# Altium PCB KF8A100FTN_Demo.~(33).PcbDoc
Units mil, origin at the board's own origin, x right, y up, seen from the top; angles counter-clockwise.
Board outline 6000 x 4000 mil, 2 copper layers (Top Layer, Bottom Layer); 25 components, 35 nets, 113 pads, 0 vias.
Unrouted connection lines stored in the file: 7.
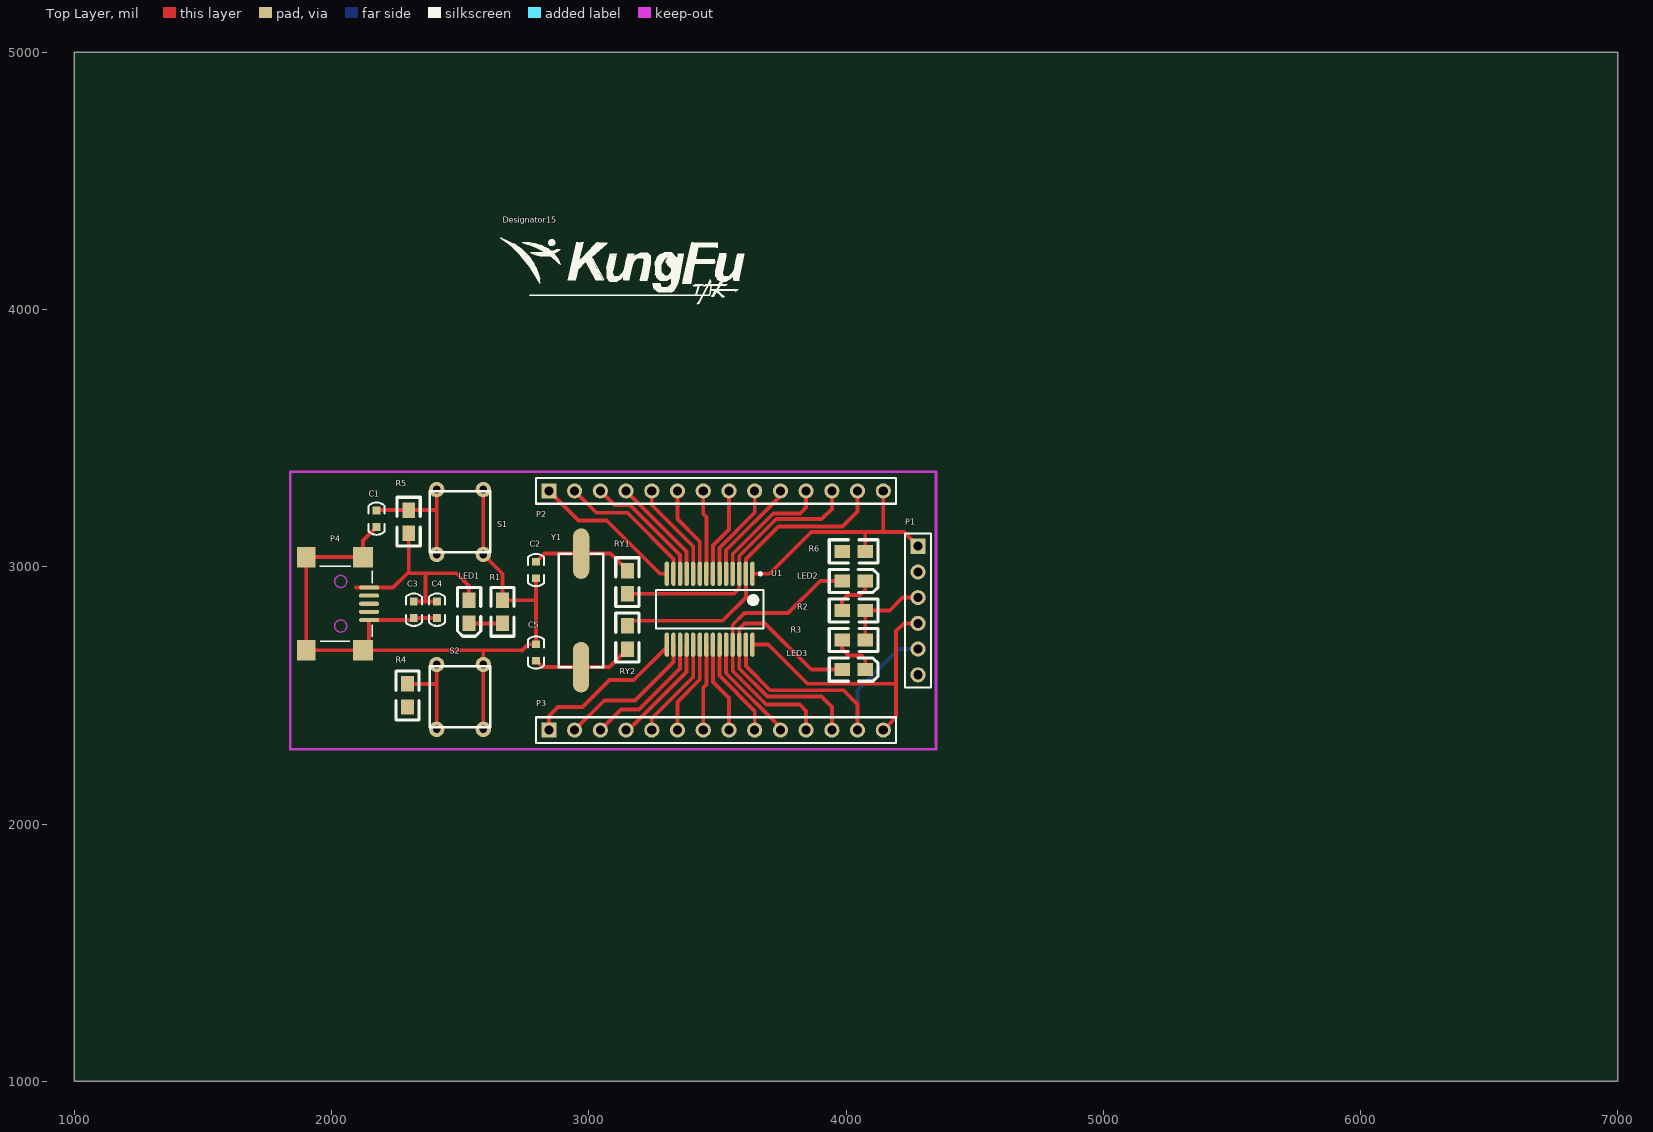
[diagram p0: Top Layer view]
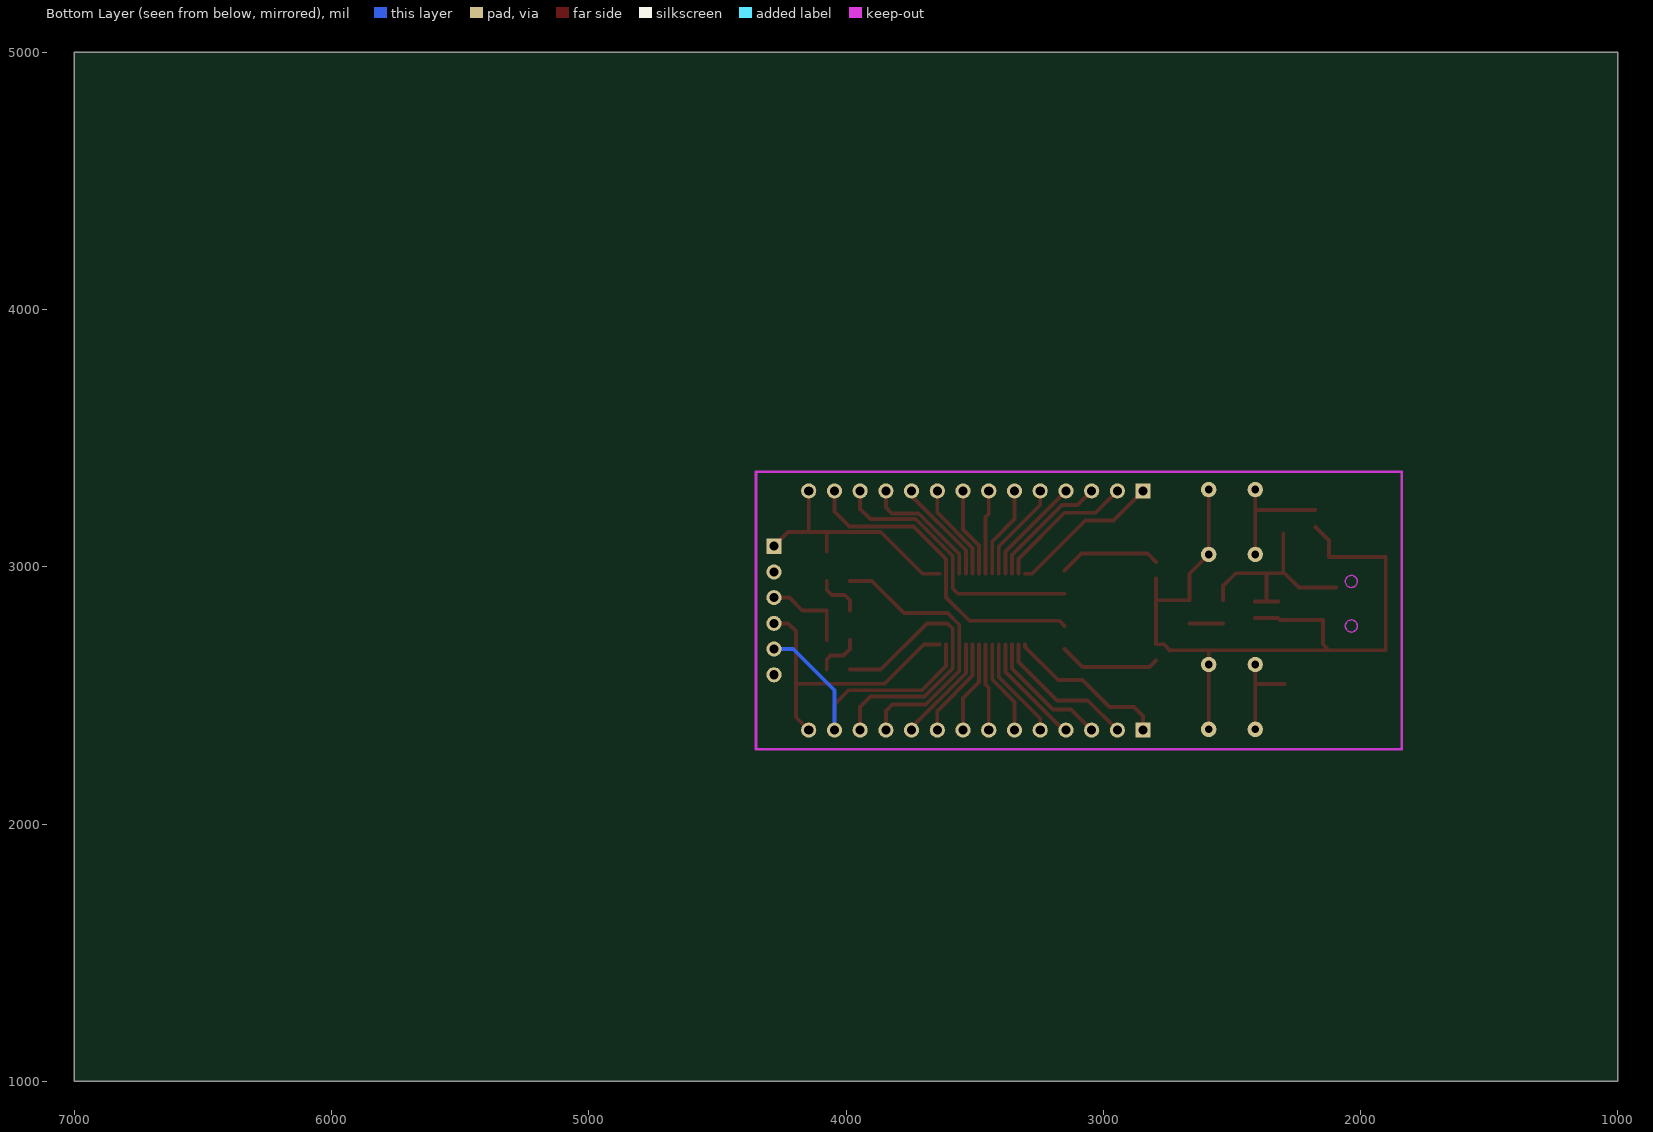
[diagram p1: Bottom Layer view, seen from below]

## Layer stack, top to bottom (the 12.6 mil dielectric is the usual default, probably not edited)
Top Solder: solder mask 0.4, Solder Resist, Dk 3.5
Top Layer: signal copper 1.4
Dielectric 1: dielectric 12.6, FR-4, Dk 4.8
Bottom Layer: signal copper 1.4
Bottom Solder: solder mask 0.4, Solder Resist, Dk 3.5

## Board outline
1000,1000 7000,1000 7000,5000 1000,5000

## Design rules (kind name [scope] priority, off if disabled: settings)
Clearance [All] p1: gap=7
PolygonConnect [All] p1: connectstyle=Relief reliefconductorwidth=10 reliefentries=4 polygonreliefangle="90 Angle" airgapwidth=10
RoutingVias [All] p1: holewidth=28 width=50 viastyle="Through Hole" minholewidth=28 minwidth=50 maxholewidth=28 maxwidth=50
SolderMaskExpansion [All] p1: expansion=4
UnpouredPolygon [All] p1: allowunpoured=FALSE
Width [All] p1: maxlimit=30 minlimit=10 preferedwidth=15
29 further rules are at their usual default settings.

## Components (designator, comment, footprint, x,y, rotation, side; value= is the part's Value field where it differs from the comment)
C1 "Comment" 0603C 2175,3155 r90 top
C2 "Comment" 0603C 2795,2955 r90 top
C3 "Comment" 0603C 2320,2865 r270 top
C4 "Comment" 0603C 2410,2865 r270 top
C5 "Comment" 0603C 2795,2635 r90 top
Designator15 "Comment" LOGO 2770,4055 r0 top
LED1 "Comment" D0805 2535,2870 r270 top
LED2 "Comment" D0805 3984.89,2945 r0 top
LED3 "Comment" D0805 3984.89,2600 r0 top
P1 "Comment" HDR1X6 4280,3080 r270 top
P2 "Comment" HDR1X14 2845,3295 r0 top
P3 "Comment" HDR1X14 2845,2365 r0 top
P4 "Comment" USB_MINI_B 2030,2890 r0 top
R1 "Comment" 0805 2665,2780 r90 top
R2 "Comment" 0805 3985,2830 r0 top
R3 "Comment" 0805 3985,2715 r0 top
R4 "Comment" 0805 2295,2455 r90 top
R5 "Comment" 0805 2300,3220 r270 top
R6 "Comment" 0805 3985,3060 r0 top
RY1 "Comment" 0805 3150,2985 r270 top
RY2 "Comment" 0805 3150,2770 r270 top
S1 "Comment" KEY6*6 2590,3300 r270 top
S2 "Comment" KEY6*6 2590,2620 r270 top
U1 "Comment" SSOP-SS28_M 3470,2835 r270 top
Y1 "Comment" CRYSTAL 2970,2610 r90 top

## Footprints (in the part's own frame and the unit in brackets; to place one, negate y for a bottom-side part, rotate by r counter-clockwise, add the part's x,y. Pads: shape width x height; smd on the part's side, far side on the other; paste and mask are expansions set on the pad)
0603C [mil]
  rect 30x30 smd: 1(0,0) 2(64,0)
  silkscreen extent -31,-31 95,31
0805 [mil]
  rect 60x50 smd: 1(-0.11,0) 2(89.89,0)
  silkscreen extent -50,-45 140,45
CRYSTAL [mm]
  oval 5x1.6 smd: 1(0,0) 2(11.2,-0.01)
  silkscreen extent 0,-2.2 11.2,2.2
D0805 [mil]
  rect 60x50 smd: 1(0,0) 2(90,0)
  silkscreen extent -50,-45 140,45
HDR1X6 [mm] "Connector; Header; 6 Position"
  rect 1.5x1.5 hole 0.9: 1(0,0)
  round 1.5 hole 0.9: 2(2.54,0) 3(5.08,0) 4(7.62,0) 5(10.16,0) 6(12.7,0)
  silkscreen extent -1.27,-1.27 13.97,1.27
HDR1X14 [mm] "Connector; Header; 14 Position"
  rect 1.5x1.5 hole 0.9: 1(0,0)
  round 1.5 hole 0.9: 2(2.54,0) 3(5.08,0) 4(7.62,0) 5(10.16,0) 6(12.7,0) 7(15.24,0) 8(17.78,0) 9(20.32,0) 10(22.86,0) 11(25.4,0) 12(27.94,0) 13(30.48,0) 14(33.02,0)
  silkscreen extent -1.27,-1.27 34.29,1.27
KEY6*6 [mil]
  round 60 hole 30: 1(0,0) 2(0,-181.1) 3(251.97,0) 4(251.97,-181.1)
  silkscreen extent 7,-209 243,28
LOGO [mil]
  silkscreen extent -114,-33 835,225
SSOP-SS28_M [mm] "SOP, 28-Leads, Body 10.2x5.2mm, Pitch 0.65mm, IPC Low Density"
  oval 2.4x0.45 smd: 1(-3.5,4.225) 2(-3.5,3.575) 3(-3.5,2.925) 4(-3.5,2.275) 5(-3.5,1.625) 6(-3.5,0.975) 7(-3.5,0.325) 8(-3.5,-0.325) 9(-3.5,-0.975) 10(-3.5,-1.625) 11(-3.5,-2.275) 12(-3.5,-2.925) 13(-3.5,-3.575) 14(-3.5,-4.225) 15(3.5,-4.225) 16(3.5,-3.575) 17(3.5,-2.925) 18(3.5,-2.275) 19(3.5,-1.625) 20(3.5,-0.975) 21(3.5,-0.325) 22(3.5,0.325) 23(3.5,0.975) 24(3.5,1.625) 25(3.5,2.275) 26(3.5,2.925) 27(3.5,3.575) 28(3.5,4.225)
  silkscreen extent -3.62,-5.3 1.9,5.3, body extent -2.7,-5.3 2.7,5.3, height 2
USB_MINI_B [mm] "USB_MINI_B"
  oval 2x0.4 smd: 1(2.941,0.744) 2(2.941,-0.056) 3(2.941,-0.856) 4(2.941,-1.656) 5(2.941,-2.456)
  rect 1.797x2 smd: 6(-3.259,-5.456) 6(-3.259,3.744)
  rect 2x2 smd: 6(2.341,-5.456) 6(2.341,3.744)
  Keep-Out Layer circle w0.127: c0.141,1.344 r0.6
  Keep-Out Layer circle w0.127: c0.141,-3.056 r0.6
  silkscreen extent -1.93,-4.58 3.24,2.85

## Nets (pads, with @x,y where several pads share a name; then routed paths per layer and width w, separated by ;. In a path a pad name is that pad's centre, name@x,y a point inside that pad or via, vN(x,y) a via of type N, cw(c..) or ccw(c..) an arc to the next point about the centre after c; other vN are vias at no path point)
L1: LED1.2 R1.1 | length 130
  Top Layer w15: LED1.2 2664.89,2780 R1.1
L2: LED2.2 R2.1 | length 181.6
  Top Layer w15: R2.1 3984.89,2869.89 4005,2890 4055,2890 4074.89,2909.89 LED2.2
L3: LED3.2 R3.1 | length 181.6
  Top Layer w15: R3.1 3984.89,2680.11 4010,2655 4060,2655 4074.89,2640.11 LED3.2
P04: P2.13 RY2.1 U1.2 | length 1247.1
  Top Layer w15: RY2.1 3169.89,2790 3520,2790 3610.75,2880.75 U1.2 3610.75,3030.75 3737,3157 3987,3157 4045,3215 P2.13
P05: P2.12 RY1.2 U1.3 | length 1075.5
  Top Layer w15: RY1.2 3565.11,2895.11 3585.16,2915.16 U1.3 3585.16,3041.27 3728.89,3185 3905,3185 3945,3225 P2.12
P10: P3.4 U1.18 | length 435.6
  Top Layer w15: P3.4 3155,2365 3380.43,2590.43 U1.18
P11: P3.3 U1.17 | length 501.6
  Top Layer w15: P3.3 3125,2445 3195,2445 3354.84,2604.84 U1.17
P12: P3.2 U1.16 | length 561.7
  Top Layer w15: P3.2 3060,2480 3180,2480 3329.25,2629.25 U1.16
P13: P3.1 U1.15 | length 633.5
  Top Layer w15: P3.1 2845,2420 2880,2455 2975,2455 3080,2560 3175,2560 3303.66,2688.66 U1.15
P14: P2.1 U1.14 | length 592.1
  Top Layer w15: P2.1 2960,3180 3070,3180 3277.2,2972.8 U1.14
P15: P2.2 U1.13 | length 551.7
  Top Layer w15: P2.2 3030,3210 3150,3210 3329.25,3030.75 U1.13
P16: P2.3 U1.12 | length 485.7
  Top Layer w15: P2.3 3100,3240 3160,3240 3354.84,3045.16 U1.12
P17: P2.4 U1.11 | length 419.7
  Top Layer w15: P2.4 3380.43,3059.57 U1.11
P20: P2.11 U1.4 | length 501.9
  Top Layer w15: U1.4 3559.57,3049.57 3717,3207 3822,3207 3845,3230 P2.11
P21: P2.10 U1.5 | length 409.6
  Top Layer w15: U1.5 3533.98,3063.98 3745,3275 P2.10
P22: P2.9 U1.6 | length 378.8
  Top Layer w15: U1.6 3508.39,3073.39 3645,3210 P2.9
P23: P2.8 U1.7 | length 348
  Top Layer w15: U1.7 3482.8,3082.8 3545,3145 P2.8
P24: P2.7 U1.8 | length 327.3
  Top Layer w15: P2.7 3445,3205 3457.2,3192.8 U1.8
P25: P2.6 U1.9 | length 358.1
  Top Layer w15: P2.6 3345,3185 3431.61,3098.39 U1.9
P26: P2.5 R4.2 S2.2 S2.4 U1.10 | length 754.8
  Top Layer w15: R4.2 2408.79,2544.89 2408.9,2545 ; S2.4 2408.9,2545 ; S2.2 2408.9,2545 ; P2.5 3245,3240 3406.02,3078.98 U1.10
P30: LED3.1 P3.12 U1.26 | length 1149.7
  Top Layer w15: P3.12 3945,2455 3905,2495 3695,2495 3585.16,2604.84 U1.26 3585.16,2760.16 3605,2780 3685,2780 3865,2600 LED3.1
P31: LED2.1 P3.11 U1.25 | length 1099.9
  Top Layer w15: P3.11 3845,2440 3820,2465 3690,2465 3559.57,2595.43 U1.25 3559.57,2774.57 3605,2820 3775,2820 3900,2945 LED2.1
P32: P3.10 U1.24 | length 419.6
  Top Layer w15: U1.24 3533.98,2586.02 3745,2375 P3.10
P33: P3.9 U1.23 | length 388.8
  Top Layer w15: U1.23 3508.39,2576.61 3645,2440 P3.9
P34: P3.8 U1.22 | length 358
  Top Layer w15: U1.22 3482.8,2552.2 3545,2490 P3.8
P35: P3.7 U1.21 | length 337.3
  Top Layer w15: P3.7 3445,2530 3457.2,2542.2 U1.21
RST: P1.1 P2.14 R6.2 U1.1 | length 970.7
  Top Layer w15: U1.1 3702.8,2972.8 3865,3135 4070,3135 ; R6.2 4074.89,3130.11 4070,3135 ; P2.14 4145,3135 ; P1.1 4225,3135 4145,3135 ; 4070,3135 4145,3135
S2: C1.2 R5.1 R6.1 S1.2 S1.4 | length 479.9
  Top Layer w15: C1.2@2176.11,3220.11 R5.1 2404.01,3220.11 ; S1.4 S1.2
S2-1: 
SPCLK: P1.5 P3.13 U1.27 | length 1135.3
  Top Layer w15: U1.27 3610.75,2614.25 3705,2520 3990,2520 4045,2465 P3.13
  Bottom Layer w15: P3.13 4045,2520 4205,2680 P1.5
SPDAT: P1.4 P3.14 U1.28 | length 1119.8
  Top Layer w15: U1.28 3697.8,2697.2 3850,2545 4190,2545 ; P3.14 4195,2415 4195,2750 4225,2780 P1.4
VDD: C3.1 C4.1 LED1.1 P1.2 P3.6 P4.1 R4.1 R5.2 U1.20 | length 1264.8
  Top Layer w15: 2094.28,2919.28 P4.1 2239.28,2919.28 2295,2975 ; R5.2 2300,2980 2295,2975 ; C3.1 2365,2865 ; C4.1 2365,2865 ; LED1.1 2535,2925 2485,2975 2365,2975 ; P3.6 3345,2475 3431.61,2561.61 U1.20 ; 2295,2975 2365,2975 ; 2365,2865 2365,2975
VSS: C1.1 C2.1 C3.2 C4.2 C5.2 P1.3 P3.5 P4.5 P4.6 R1.2 R2.2 R3.2 S1.1 S1.3 S2.1 S2.3 U1.19 | length 3909.6
  Top Layer w15: C1.1 2122.18,3102.18 2122.18,3037.39 1901.71,3037.39 1901.71,2675.19 P4.6@2122.18,2675.19 ; C4.2 C3.2 2312.3,2793.3 P4.5 2145.8,2698.81 P4.6@2122.18,2675.19 ; S2.3 S2.1 2590,2670.19 ; S1.1 S1.3 2665,2973.03 R1.2 2794.89,2869.89 2795,2870 ; 2739.81,2675.19 P4.6@2122.18,2675.19 ; 2740,2675 2764,2699 C5.2 2795,2870 ; C2.1 2795,2870 ; P3.5 3245,2410 3406.02,2571.02 U1.19 ; R3.2 R2.2 4170,2830 4220,2880 P1.3
Y1: C5.1 RY2.2 Y1.1 | length 394.4
  Top Layer w15: C5.1 2820,2610 Y1.1 3079.89,2610 RY2.2
Y2: C2.2 RY1.1 Y1.2 | length 395.5
  Top Layer w15: C2.2 2826.95,3050.95 Y1.2 3084.16,3050.95 RY1.1
pads on no net: P1.6 P4.2 P4.3 P4.4

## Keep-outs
Keep-Out Layer:
  lines w10: 1840,2290 4350,2290 4350,3370 1840,3370 1840,2290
